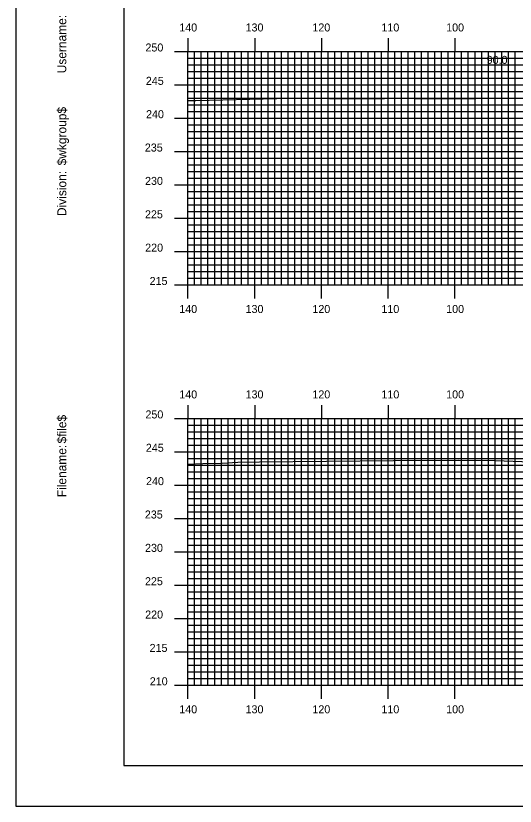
# Model space of a CAD drawing. Extents: x 1816883 to 1817226, y 442591 to 442811.
# Drawn here: x 1816882.8 to 1816957.6, y 442590.5 to 442709 of the extents above; entities that cross this region are included whole.
import ezdxf

# ---------------------------------------------------------------- set-up
doc = ezdxf.new("R2010")
doc.units = 0
for name, color, linetype in [('BORDER', 7, 'Continuous'), ('D_Text_Standard', 7, 'Continuous'), ('H_V ANNOTATION', 7, 'Continuous'), ('MAJOR', 7, 'Continuous'), ('MINOR', 7, 'Continuous'), ('PLOT BOUNDARY', 7, 'Continuous'), ('S_Roadway_Centerline', 7, 'Continuous')]:
    doc.layers.add(name, color=color, linetype=linetype)

msp = doc.modelspace()

# ---------------------------------------------------------------- linework, layer by layer
at = {"layer": 'BORDER'}
msp.add_lwpolyline([(1816898.99, 442596.67), (1817218.99, 442596.67), (1817218.99, 442806.67), (1816898.99, 442806.67)], close=True, dxfattribs=at)
at = {"layer": 'MAJOR'}
for p, q in [((1816908.59, 442705.67), (1816908.59, 442703.67)), ((1816918.59, 442705.67), (1816918.59, 442703.67)), ((1816928.59, 442705.67), (1816928.59, 442703.67)), ((1816938.59, 442705.67), (1816938.59, 442703.67)), ((1816948.59, 442705.67), (1816948.59, 442703.67)), ((1816906.58, 442703.67), (1816908.59, 442703.67)), ((1816908.59, 442703.67), (1817188.59, 442703.67)), ((1816908.59, 442668.67), (1816908.59, 442703.67)), ((1816908.59, 442668.67), (1816908.59, 442703.67)), ((1816908.59, 442703.67), (1817188.59, 442703.67)), ((1816918.59, 442668.67), (1816918.59, 442703.67)), ((1816928.59, 442668.67), (1816928.59, 442703.67)), ((1816938.59, 442668.67), (1816938.59, 442703.67)), ((1816948.59, 442668.67), (1816948.59, 442703.67)), ((1816906.58, 442698.67), (1816908.59, 442698.67)), ((1816908.59, 442698.67), (1817188.59, 442698.67)), ((1816906.58, 442693.67), (1816908.59, 442693.67)), ((1816908.59, 442693.67), (1817188.59, 442693.67)), ((1816906.58, 442688.67), (1816908.59, 442688.67)), ((1816908.59, 442688.67), (1817188.59, 442688.67)), ((1816906.58, 442683.67), (1816908.59, 442683.67)), ((1816908.59, 442683.67), (1817188.59, 442683.67)), ((1816906.58, 442678.67), (1816908.59, 442678.67)), ((1816908.59, 442678.67), (1817188.59, 442678.67)), ((1816906.58, 442673.67), (1816908.59, 442673.67)), ((1816908.59, 442673.67), (1817188.59, 442673.67)), ((1816906.58, 442668.67), (1816908.59, 442668.67)), ((1816908.59, 442668.67), (1817188.59, 442668.67)), ((1816908.59, 442668.67), (1817188.59, 442668.67)), ((1816908.59, 442666.66), (1816908.59, 442668.67)), ((1816918.59, 442666.66), (1816918.59, 442668.67)), ((1816928.59, 442666.66), (1816928.59, 442668.67)), ((1816938.59, 442666.66), (1816938.59, 442668.67)), ((1816948.59, 442666.66), (1816948.59, 442668.67)), ((1816908.59, 442650.67), (1816908.59, 442648.67)), ((1816918.59, 442650.67), (1816918.59, 442648.67)), ((1816928.59, 442650.67), (1816928.59, 442648.67)), ((1816938.59, 442650.67), (1816938.59, 442648.67)), ((1816948.59, 442650.67), (1816948.59, 442648.67)), ((1816906.58, 442648.67), (1816908.59, 442648.67)), ((1816908.59, 442648.67), (1817188.59, 442648.67)), ((1816908.59, 442608.67), (1816908.59, 442648.67)), ((1816908.59, 442608.67), (1816908.59, 442648.67)), ((1816908.59, 442648.67), (1817188.59, 442648.67)), ((1816918.59, 442608.67), (1816918.59, 442648.67)), ((1816928.59, 442608.67), (1816928.59, 442648.67)), ((1816938.59, 442608.67), (1816938.59, 442648.67)), ((1816948.59, 442608.67), (1816948.59, 442648.67)), ((1816906.58, 442643.67), (1816908.59, 442643.67)), ((1816908.59, 442643.67), (1817188.59, 442643.67)), ((1816906.58, 442638.67), (1816908.59, 442638.67)), ((1816908.59, 442638.67), (1817188.59, 442638.67)), ((1816906.58, 442633.67), (1816908.59, 442633.67)), ((1816908.59, 442633.67), (1817188.59, 442633.67)), ((1816906.58, 442628.67), (1816908.59, 442628.67)), ((1816908.59, 442628.67), (1817188.59, 442628.67)), ((1816906.58, 442623.67), (1816908.59, 442623.67)), ((1816908.59, 442623.67), (1817188.59, 442623.67)), ((1816906.58, 442618.67), (1816908.59, 442618.67)), ((1816908.59, 442618.67), (1817188.59, 442618.67)), ((1816906.58, 442613.67), (1816908.59, 442613.67)), ((1816908.59, 442613.67), (1817188.59, 442613.67)), ((1816906.58, 442608.67), (1816908.59, 442608.67)), ((1816908.59, 442608.67), (1817188.59, 442608.67)), ((1816908.59, 442608.67), (1817188.59, 442608.67)), ((1816908.59, 442606.66), (1816908.59, 442608.67)), ((1816918.59, 442606.66), (1816918.59, 442608.67)), ((1816928.59, 442606.66), (1816928.59, 442608.67)), ((1816938.59, 442606.66), (1816938.59, 442608.67)), ((1816948.59, 442606.66), (1816948.59, 442608.67))]:
    msp.add_line(p, q, dxfattribs=at)
at = {"layer": 'MINOR'}
for p, q in [((1816909.59, 442668.67), (1816909.59, 442703.67)), ((1816910.59, 442668.67), (1816910.59, 442703.67)), ((1816911.59, 442668.67), (1816911.59, 442703.67)), ((1816912.59, 442668.67), (1816912.59, 442703.67)), ((1816913.59, 442668.67), (1816913.59, 442703.67)), ((1816914.59, 442668.67), (1816914.59, 442703.67)), ((1816915.59, 442668.67), (1816915.59, 442703.67)), ((1816916.59, 442668.67), (1816916.59, 442703.67)), ((1816917.59, 442668.67), (1816917.59, 442703.67)), ((1816919.59, 442668.67), (1816919.59, 442703.67)), ((1816920.59, 442668.67), (1816920.59, 442703.67)), ((1816921.59, 442668.67), (1816921.59, 442703.67)), ((1816922.59, 442668.67), (1816922.59, 442703.67)), ((1816923.59, 442668.67), (1816923.59, 442703.67)), ((1816924.59, 442668.67), (1816924.59, 442703.67)), ((1816925.59, 442668.67), (1816925.59, 442703.67)), ((1816926.59, 442668.67), (1816926.59, 442703.67)), ((1816927.59, 442668.67), (1816927.59, 442703.67)), ((1816929.59, 442668.67), (1816929.59, 442703.67)), ((1816930.59, 442668.67), (1816930.59, 442703.67)), ((1816931.59, 442668.67), (1816931.59, 442703.67)), ((1816932.59, 442668.67), (1816932.59, 442703.67)), ((1816933.59, 442668.67), (1816933.59, 442703.67)), ((1816934.59, 442668.67), (1816934.59, 442703.67)), ((1816935.59, 442668.67), (1816935.59, 442703.67)), ((1816936.59, 442668.67), (1816936.59, 442703.67)), ((1816937.59, 442668.67), (1816937.59, 442703.67)), ((1816939.59, 442668.67), (1816939.59, 442703.67)), ((1816940.59, 442668.67), (1816940.59, 442703.67)), ((1816941.59, 442668.67), (1816941.59, 442703.67)), ((1816942.59, 442668.67), (1816942.59, 442703.67)), ((1816943.59, 442668.67), (1816943.59, 442703.67)), ((1816944.59, 442668.67), (1816944.59, 442703.67)), ((1816945.59, 442668.67), (1816945.59, 442703.67)), ((1816946.59, 442668.67), (1816946.59, 442703.67)), ((1816947.59, 442668.67), (1816947.59, 442703.67)), ((1816949.59, 442668.67), (1816949.59, 442703.67)), ((1816950.59, 442668.67), (1816950.59, 442703.67)), ((1816951.59, 442668.67), (1816951.59, 442703.67)), ((1816952.59, 442668.67), (1816952.59, 442703.67)), ((1816953.59, 442668.67), (1816953.59, 442703.67)), ((1816954.59, 442668.67), (1816954.59, 442703.67)), ((1816955.59, 442668.67), (1816955.59, 442703.67)), ((1816956.59, 442668.67), (1816956.59, 442703.67)), ((1816957.59, 442668.67), (1816957.59, 442703.67)), ((1816908.59, 442702.67), (1817188.59, 442702.67)), ((1816908.59, 442702.67), (1816910.59, 442702.67)), ((1816908.59, 442701.67), (1817188.59, 442701.67)), ((1816908.59, 442701.67), (1816910.59, 442701.67)), ((1816908.59, 442700.67), (1817188.59, 442700.67)), ((1816908.59, 442700.67), (1816910.59, 442700.67)), ((1816908.59, 442699.67), (1817188.59, 442699.67)), ((1816908.59, 442699.67), (1816910.59, 442699.67)), ((1816908.59, 442697.67), (1817188.59, 442697.67)), ((1816908.59, 442697.67), (1816910.59, 442697.67)), ((1816908.59, 442696.67), (1817188.59, 442696.67)), ((1816908.59, 442696.67), (1816910.59, 442696.67)), ((1816908.59, 442695.67), (1817188.59, 442695.67)), ((1816908.59, 442695.67), (1816910.59, 442695.67)), ((1816908.59, 442694.67), (1817188.59, 442694.67)), ((1816908.59, 442694.67), (1816910.59, 442694.67)), ((1816908.59, 442692.67), (1817188.59, 442692.67)), ((1816908.59, 442692.67), (1816910.59, 442692.67)), ((1816908.59, 442691.67), (1817188.59, 442691.67)), ((1816908.59, 442691.67), (1816910.59, 442691.67)), ((1816908.59, 442690.67), (1817188.59, 442690.67)), ((1816908.59, 442690.67), (1816910.59, 442690.67)), ((1816908.59, 442689.67), (1817188.59, 442689.67)), ((1816908.59, 442689.67), (1816910.59, 442689.67)), ((1816908.59, 442687.67), (1817188.59, 442687.67)), ((1816908.59, 442687.67), (1816910.59, 442687.67)), ((1816908.59, 442686.67), (1817188.59, 442686.67)), ((1816908.59, 442686.67), (1816910.59, 442686.67)), ((1816908.59, 442685.67), (1817188.59, 442685.67)), ((1816908.59, 442685.67), (1816910.59, 442685.67)), ((1816908.59, 442684.67), (1817188.59, 442684.67)), ((1816908.59, 442684.67), (1816910.59, 442684.67)), ((1816908.59, 442682.67), (1817188.59, 442682.67)), ((1816908.59, 442682.67), (1816910.59, 442682.67)), ((1816908.59, 442681.67), (1817188.59, 442681.67)), ((1816908.59, 442681.67), (1816910.59, 442681.67)), ((1816908.59, 442680.67), (1817188.59, 442680.67)), ((1816908.59, 442680.67), (1816910.59, 442680.67)), ((1816908.59, 442679.67), (1817188.59, 442679.67)), ((1816908.59, 442679.67), (1816910.59, 442679.67)), ((1816908.59, 442677.67), (1817188.59, 442677.67)), ((1816908.59, 442677.67), (1816910.59, 442677.67)), ((1816908.59, 442676.67), (1817188.59, 442676.67)), ((1816908.59, 442676.67), (1816910.59, 442676.67)), ((1816908.59, 442675.67), (1817188.59, 442675.67)), ((1816908.59, 442675.67), (1816910.59, 442675.67)), ((1816908.59, 442674.67), (1817188.59, 442674.67)), ((1816908.59, 442674.67), (1816910.59, 442674.67)), ((1816908.59, 442672.67), (1817188.59, 442672.67)), ((1816908.59, 442672.67), (1816910.59, 442672.67)), ((1816908.59, 442671.67), (1817188.59, 442671.67)), ((1816908.59, 442671.67), (1816910.59, 442671.67)), ((1816908.59, 442670.67), (1817188.59, 442670.67)), ((1816908.59, 442670.67), (1816910.59, 442670.67)), ((1816908.59, 442669.67), (1817188.59, 442669.67)), ((1816908.59, 442669.67), (1816910.59, 442669.67)), ((1816908.59, 442647.67), (1817188.59, 442647.67)), ((1816908.59, 442647.67), (1816910.59, 442647.67)), ((1816909.59, 442608.67), (1816909.59, 442648.67)), ((1816910.59, 442608.67), (1816910.59, 442648.67)), ((1816911.59, 442608.67), (1816911.59, 442648.67)), ((1816912.59, 442608.67), (1816912.59, 442648.67)), ((1816913.59, 442608.67), (1816913.59, 442648.67)), ((1816914.59, 442608.67), (1816914.59, 442648.67)), ((1816915.59, 442608.67), (1816915.59, 442648.67)), ((1816916.59, 442608.67), (1816916.59, 442648.67)), ((1816917.59, 442608.67), (1816917.59, 442648.67)), ((1816919.59, 442608.67), (1816919.59, 442648.67)), ((1816920.59, 442608.67), (1816920.59, 442648.67)), ((1816921.59, 442608.67), (1816921.59, 442648.67)), ((1816922.59, 442608.67), (1816922.59, 442648.67)), ((1816923.59, 442608.67), (1816923.59, 442648.67)), ((1816924.59, 442608.67), (1816924.59, 442648.67)), ((1816925.59, 442608.67), (1816925.59, 442648.67)), ((1816926.59, 442608.67), (1816926.59, 442648.67)), ((1816927.59, 442608.67), (1816927.59, 442648.67)), ((1816929.59, 442608.67), (1816929.59, 442648.67)), ((1816930.59, 442608.67), (1816930.59, 442648.67)), ((1816931.59, 442608.67), (1816931.59, 442648.67)), ((1816932.59, 442608.67), (1816932.59, 442648.67)), ((1816933.59, 442608.67), (1816933.59, 442648.67)), ((1816934.59, 442608.67), (1816934.59, 442648.67)), ((1816935.59, 442608.67), (1816935.59, 442648.67)), ((1816936.59, 442608.67), (1816936.59, 442648.67)), ((1816937.59, 442608.67), (1816937.59, 442648.67)), ((1816939.59, 442608.67), (1816939.59, 442648.67)), ((1816940.59, 442608.67), (1816940.59, 442648.67)), ((1816941.59, 442608.67), (1816941.59, 442648.67)), ((1816942.59, 442608.67), (1816942.59, 442648.67)), ((1816943.59, 442608.67), (1816943.59, 442648.67)), ((1816944.59, 442608.67), (1816944.59, 442648.67)), ((1816945.59, 442608.67), (1816945.59, 442648.67)), ((1816946.59, 442608.67), (1816946.59, 442648.67)), ((1816947.59, 442608.67), (1816947.59, 442648.67)), ((1816949.59, 442608.67), (1816949.59, 442648.67)), ((1816950.59, 442608.67), (1816950.59, 442648.67)), ((1816951.59, 442608.67), (1816951.59, 442648.67)), ((1816952.59, 442608.67), (1816952.59, 442648.67)), ((1816953.59, 442608.67), (1816953.59, 442648.67)), ((1816954.59, 442608.67), (1816954.59, 442648.67)), ((1816955.59, 442608.67), (1816955.59, 442648.67)), ((1816956.59, 442608.67), (1816956.59, 442648.67)), ((1816957.59, 442608.67), (1816957.59, 442648.67)), ((1816908.59, 442646.67), (1817188.59, 442646.67)), ((1816908.59, 442646.67), (1816910.59, 442646.67)), ((1816908.59, 442645.67), (1817188.59, 442645.67)), ((1816908.59, 442645.67), (1816910.59, 442645.67)), ((1816908.59, 442644.67), (1817188.59, 442644.67)), ((1816908.59, 442644.67), (1816910.59, 442644.67)), ((1816908.59, 442642.67), (1817188.59, 442642.67)), ((1816908.59, 442642.67), (1816910.59, 442642.67)), ((1816908.59, 442641.67), (1817188.59, 442641.67)), ((1816908.59, 442641.67), (1816910.59, 442641.67)), ((1816908.59, 442640.67), (1817188.59, 442640.67)), ((1816908.59, 442640.67), (1816910.59, 442640.67)), ((1816908.59, 442639.67), (1817188.59, 442639.67)), ((1816908.59, 442639.67), (1816910.59, 442639.67)), ((1816908.59, 442637.67), (1817188.59, 442637.67)), ((1816908.59, 442637.67), (1816910.59, 442637.67)), ((1816908.59, 442636.67), (1817188.59, 442636.67)), ((1816908.59, 442636.67), (1816910.59, 442636.67)), ((1816908.59, 442635.67), (1817188.59, 442635.67)), ((1816908.59, 442635.67), (1816910.59, 442635.67)), ((1816908.59, 442634.67), (1817188.59, 442634.67)), ((1816908.59, 442634.67), (1816910.59, 442634.67)), ((1816908.59, 442632.67), (1817188.59, 442632.67)), ((1816908.59, 442632.67), (1816910.59, 442632.67)), ((1816908.59, 442631.67), (1817188.59, 442631.67)), ((1816908.59, 442631.67), (1816910.59, 442631.67)), ((1816908.59, 442630.67), (1817188.59, 442630.67)), ((1816908.59, 442630.67), (1816910.59, 442630.67)), ((1816908.59, 442629.67), (1817188.59, 442629.67)), ((1816908.59, 442629.67), (1816910.59, 442629.67)), ((1816908.59, 442627.67), (1817188.59, 442627.67)), ((1816908.59, 442627.67), (1816910.59, 442627.67)), ((1816908.59, 442626.67), (1817188.59, 442626.67)), ((1816908.59, 442626.67), (1816910.59, 442626.67)), ((1816908.59, 442625.67), (1817188.59, 442625.67)), ((1816908.59, 442625.67), (1816910.59, 442625.67)), ((1816908.59, 442624.67), (1817188.59, 442624.67)), ((1816908.59, 442624.67), (1816910.59, 442624.67)), ((1816908.59, 442622.67), (1817188.59, 442622.67)), ((1816908.59, 442622.67), (1816910.59, 442622.67)), ((1816908.59, 442621.67), (1817188.59, 442621.67)), ((1816908.59, 442621.67), (1816910.59, 442621.67)), ((1816908.59, 442620.67), (1817188.59, 442620.67)), ((1816908.59, 442620.67), (1816910.59, 442620.67)), ((1816908.59, 442619.67), (1817188.59, 442619.67)), ((1816908.59, 442619.67), (1816910.59, 442619.67)), ((1816908.59, 442617.67), (1817188.59, 442617.67)), ((1816908.59, 442617.67), (1816910.59, 442617.67)), ((1816908.59, 442616.67), (1817188.59, 442616.67)), ((1816908.59, 442616.67), (1816910.59, 442616.67)), ((1816908.59, 442615.67), (1817188.59, 442615.67)), ((1816908.59, 442615.67), (1816910.59, 442615.67)), ((1816908.59, 442614.67), (1817188.59, 442614.67)), ((1816908.59, 442614.67), (1816910.59, 442614.67)), ((1816908.59, 442612.67), (1817188.59, 442612.67)), ((1816908.59, 442612.67), (1816910.59, 442612.67)), ((1816908.59, 442611.67), (1817188.59, 442611.67)), ((1816908.59, 442611.67), (1816910.59, 442611.67)), ((1816908.59, 442610.67), (1817188.59, 442610.67)), ((1816908.59, 442610.67), (1816910.59, 442610.67)), ((1816908.59, 442609.67), (1817188.59, 442609.67)), ((1816908.59, 442609.67), (1816910.59, 442609.67))]:
    msp.add_line(p, q, dxfattribs=at)
at = {"layer": 'PLOT BOUNDARY'}
msp.add_lwpolyline([(1816882.8, 442590.55), (1817222.8, 442590.55), (1817222.8, 442810.55), (1816882.8, 442810.55)], close=True, dxfattribs=at)
at = {"layer": 'S_Roadway_Centerline'}
for points in [[(1816908.59, 442696.31), (1816909.76, 442696.33), (1816921.9, 442696.64), (1816922.72, 442696.66), (1816922.98, 442696.66), (1816936.52, 442696.55), (1816939.59, 442696.67), (1816945.61, 442696.57), (1816957.82, 442696.65)], [(1816908.59, 442641.83), (1816910.83, 442641.89), (1816913.72, 442641.96), (1816916.04, 442642.1), (1816919.32, 442642.17), (1816939.36, 442642.34), (1816949.14, 442642.41), (1816954.65, 442642.34), (1816962.57, 442642.05)]]:
    msp.add_lwpolyline(points, dxfattribs=at)

# ---------------------------------------------------------------- texts
at = {"layer": 'BORDER'}
for s, p in [('Username:', (1816890.36, 442700.4)), ('$wkgroup$', (1816890.36, 442686.6)), ('Division:', (1816890.36, 442679)), ('$file$', (1816890.36, 442644.92)), ('Filename:', (1816890.36, 442636.86))]:
    msp.add_text(s, height=1.339, rotation=90, dxfattribs=at).set_placement(p)
at = {"layer": 'D_Text_Standard'}
msp.add_text("90.0'", height=1.2, dxfattribs=at).set_placement((1816953.34, 442701.81))
at = {"layer": 'H_V ANNOTATION'}
for s, p in [('140', (1816907.29, 442706.67)), ('130', (1816917.22, 442706.67)), ('120', (1816927.23, 442706.67)), ('110', (1816937.57, 442706.67)), ('100', (1816947.27, 442706.67)), ('250', (1816902.22, 442703.67)), ('245', (1816902.28, 442698.67)), ('240', (1816902.31, 442693.67)), ('235', (1816902.13, 442688.67)), ('230', (1816902.16, 442683.67)), ('225', (1816902.15, 442678.67)), ('220', (1816902.18, 442673.67)), ('215', (1816902.84, 442668.67)), ('140', (1816907.29, 442664.47)), ('130', (1816917.22, 442664.47)), ('120', (1816927.23, 442664.47)), ('110', (1816937.57, 442664.47)), ('100', (1816947.27, 442664.47)), ('140', (1816907.29, 442651.67)), ('130', (1816917.22, 442651.67)), ('120', (1816927.23, 442651.67)), ('110', (1816937.57, 442651.67)), ('100', (1816947.27, 442651.67)), ('250', (1816902.22, 442648.67)), ('245', (1816902.28, 442643.67)), ('240', (1816902.31, 442638.67)), ('235', (1816902.13, 442633.67)), ('230', (1816902.16, 442628.67)), ('225', (1816902.15, 442623.67)), ('220', (1816902.18, 442618.67)), ('215', (1816902.84, 442613.67)), ('210', (1816902.87, 442608.67)), ('140', (1816907.29, 442604.47)), ('130', (1816917.22, 442604.47)), ('120', (1816927.23, 442604.47)), ('110', (1816937.57, 442604.47)), ('100', (1816947.27, 442604.47))]:
    msp.add_text(s, height=1.2, dxfattribs=at).set_placement(p)
at = {"layer": 'MAJOR'}
for p in [(1816908.58, 442668.67), (1816908.58, 442608.67)]:
    msp.add_text('-', height=0.012, dxfattribs=at).set_placement(p)

doc.saveas('drawing.dxf')
